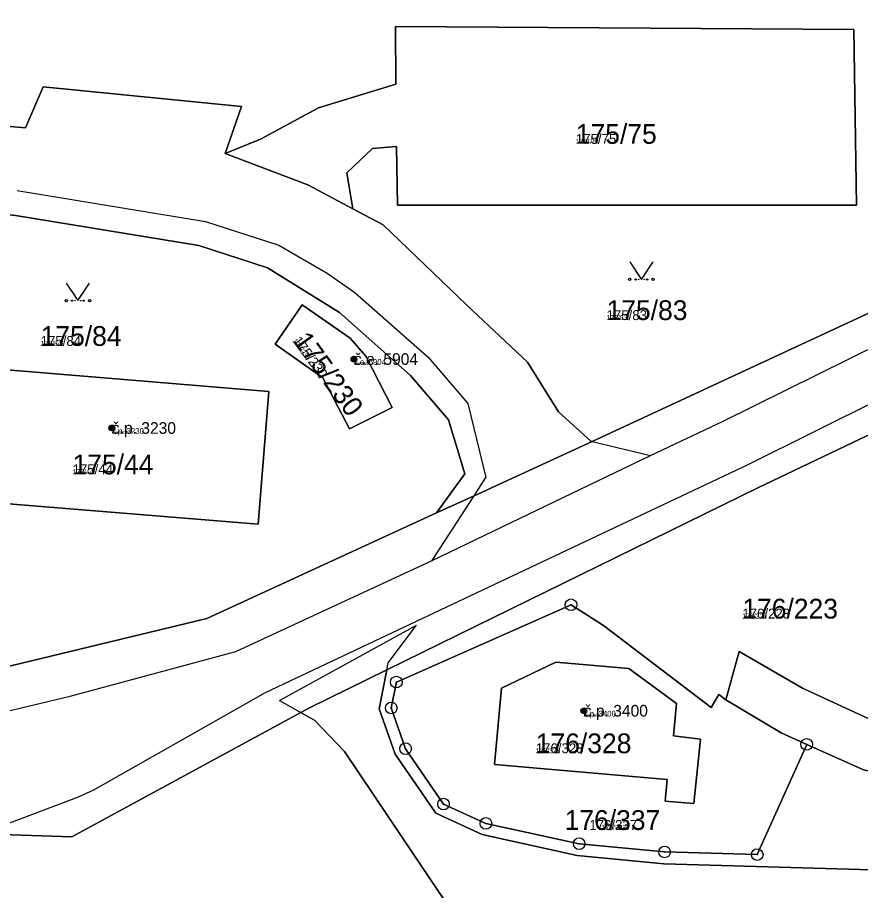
# Model space of a CAD drawing. Extents: x -759873 to -758487, y -975024 to -973516.
# Drawn here: x -759456.7 to -759384.3, y -974781.5 to -974706.5 of the extents above; entities that cross this region are included whole.
import ezdxf

# ---------------------------------------------------------------- set-up
doc = ezdxf.new("R2010")
doc.units = 0
for name, color, linetype in [('KAT_02_hranice parcel', 7, 'Continuous'), ('KAT_03_1000_st čísla parcelní', 7, 'Continuous'), ('KAT_03_1000_čísla parcelní', 7, 'Continuous'), ('KAT_03_1000_čísla popisná', 7, 'Continuous'), ('KAT_03_250_st čísla parcelní', 7, 'Continuous'), ('KAT_03_250_čísla parcelní', 7, 'Continuous'), ('KAT_03_250_čísla popisná', 7, 'Continuous'), ('KAT_03_500_st čísla parcelní', 7, 'Continuous'), ('KAT_03_500_čísla parcelní', 7, 'Continuous'), ('KAT_03_500_čísla popisná', 7, 'Continuous'), ('KAT_04_vnitřní kresba', 7, 'Continuous'), ('KAT_05_1000_značky kultur', 7, 'Continuous'), ('KAT_05_250_značky kultur', 7, 'Continuous'), ('KAT_05_500_značky kultur', 7, 'Continuous'), ('KAT_07_1000_značky budov', 7, 'Continuous'), ('KAT_07_250_značky budov', 7, 'Continuous'), ('KAT_07_500_značky budov', 7, 'Continuous'), ('KAT_11_značky bodu BP', 7, 'Continuous'), ('KAT_14_plocha_budovy', 7, 'Continuous'), ('KAT_14_plocha_pozemek', 7, 'Continuous')]:
    doc.layers.add(name, color=color, linetype=linetype)

msp = doc.modelspace()

# ---------------------------------------------------------------- linework, layer by layer
at = {"layer": 'KAT_02_hranice parcel'}
for points in [[(-759427.86, -974722.89), (-759428.36, -974719.79), (-759426.17, -974717.72), (-759424.11, -974717.53), (-759424.01, -974722.57), (-759384.61, -974722.59), (-759384.82, -974707.48), (-759424.18, -974707.23), (-759424.16, -974712.19), (-759430.82, -974714.21), (-759435.8, -974716.91), (-759438.82, -974718.15)], [(-759438.82, -974718.15), (-759437.43, -974714.11), (-759454.46, -974712.4), (-759455.96, -974715.95), (-759470.55, -974714.66), (-759468.01, -974711.71)], [(-759427.86, -974722.89), (-759431.72, -974720.83), (-759438.82, -974718.15)], [(-759338.69, -974720.79), (-759368.71, -974735.24), (-759393.08, -974746.85), (-759424.93, -974762.5)], [(-759407.29, -974742.88), (-759370.17, -974725.64), (-759360.14, -974721.06)], [(-759471.04, -974721.83), (-759456.84, -974723.48), (-759441.08, -974726.05), (-759435.18, -974727.96), (-759429.01, -974731.8), (-759422.91, -974737.21), (-759419.65, -974741.01), (-759418.24, -974745.66), (-759420.68, -974749.02)], [(-759407.29, -974742.88), (-759407.43, -974742.84), (-759410.19, -974740.33), (-759412.85, -974736.06), (-759418.1, -974731.15), (-759425.26, -974724.28), (-759427.86, -974722.89)], [(-759428.14, -974741.8), (-759430.42, -974737.4), (-759434.52, -974734.51), (-759432.2, -974731.13), (-759428.1, -974734), (-759426.75, -974735.54), (-759424.47, -974739.97), (-759428.14, -974741.8)], [(-759435.06, -974738.58), (-759458.61, -974736.64), (-759459.55, -974748.07), (-759436, -974749.98), (-759435.06, -974738.58)], [(-759420.68, -974749.02), (-759417.45, -974747.54), (-759407.29, -974742.88)], [(-759475.45, -974765.65), (-759470.53, -974765.37), (-759440.41, -974758.08), (-759420.68, -974749.02)], [(-759388.88, -974768.9), (-759393.13, -974778.37), (-759401.08, -974778.14), (-759408.42, -974777.43), (-759416.43, -974775.69), (-759420.07, -974774.03), (-759423.33, -974769.27), (-759424.56, -974765.77), (-759424.12, -974763.55), (-759409.12, -974756.91), (-759406.32, -974758.7), (-759397.07, -974765.74), (-759396.42, -974764.61), (-759395.83, -974765.08)], [(-759395.83, -974765.08), (-759394.67, -974760.92), (-759389.25, -974764.08), (-759382.92, -974767), (-759377.01, -974768.63)], [(-759400.31, -974768.17), (-759400.06, -974765.39), (-759404.15, -974762.39), (-759410.43, -974761.84), (-759415.09, -974764.06), (-759415.7, -974770.64), (-759400.86, -974771.92), (-759401.02, -974773.78), (-759398.56, -974773.98), (-759398.01, -974768.45), (-759400.31, -974768.17)], [(-759424.93, -974762.5), (-759431.64, -974765.8), (-759432.32, -974766.17)], [(-759424.93, -974762.5), (-759425.59, -974765.85), (-759424.23, -974769.73), (-759420.74, -974774.82), (-759416.74, -974776.65), (-759408.58, -974778.44), (-759401.14, -974779.15), (-759383.31, -974779.68), (-759360.24, -974780.18), (-759335.92, -974780.61), (-759318.75, -974781.06), (-759302.75, -974781.4)], [(-759395.83, -974765.08), (-759391.07, -974767.92), (-759388.88, -974768.9)], [(-759432.32, -974766.17), (-759452, -974776.85), (-759459.82, -974776.57), (-759471.04, -974776.07), (-759473.09, -974776.05)], [(-759413.3, -974803.92), (-759416.77, -974803.71), (-759416.1, -974790.31), (-759417.02, -974787.38), (-759418.5, -974784.52), (-759428.57, -974769.5), (-759431.12, -974766.84), (-759432.32, -974766.17)], [(-759355.39, -974773.73), (-759364.83, -974773.31), (-759375.96, -974772.8), (-759384.01, -974771.08), (-759388.88, -974768.9)]]:
    msp.add_lwpolyline(points, dxfattribs=at)
at = {"layer": 'KAT_03_1000_čísla popisná'}
for centre in [(-759427.76, -974735.8), (-759448.55, -974741.72), (-759408.02, -974766.01)]:
    msp.add_circle(centre, 0.25, dxfattribs=at)
at = {"layer": 'KAT_03_250_čísla popisná'}
for centre in [(-759427.76, -974735.8), (-759448.55, -974741.72), (-759408.02, -974766.01)]:
    msp.add_circle(centre, 0.0625, dxfattribs=at)
at = {"layer": 'KAT_03_500_čísla popisná'}
for centre in [(-759427.76, -974735.8), (-759448.55, -974741.72), (-759408.02, -974766.01)]:
    msp.add_circle(centre, 0.125, dxfattribs=at)
at = {"layer": 'KAT_04_vnitřní kresba'}
for p, q in [((-759456.68, -974721.32), (-759440.52, -974723.97)), ((-759440.52, -974723.97), (-759434.22, -974726.01)), ((-759434.22, -974726.01), (-759430.06, -974728.42)), ((-759430.06, -974728.42), (-759427.68, -974730.09)), ((-759396.05, -974741.14), (-759369.64, -974728.06)), ((-759427.68, -974730.09), (-759421.39, -974735.63)), ((-759393.91, -974744.86), (-759368.86, -974732.4)), ((-759421.39, -974735.63), (-759417.98, -974739.61)), ((-759417.98, -974739.61), (-759416.44, -974745.97)), ((-759402.28, -974744.08), (-759396.05, -974741.14)), ((-759407.29, -974742.88), (-759402.28, -974744.08)), ((-759421.03, -974753.09), (-759402.28, -974744.08)), ((-759435.37, -974764.44), (-759393.91, -974744.86)), ((-759417.45, -974747.54), (-759416.44, -974745.97)), ((-759421.03, -974753.09), (-759417.45, -974747.54)), ((-759437.91, -974760.91), (-759421.03, -974753.09)), ((-759434.15, -974765.14), (-759422.39, -974758.65)), ((-759424.81, -974761.9), (-759422.39, -974758.65)), ((-759452.12, -974764.75), (-759437.91, -974760.91)), ((-759424.93, -974762.5), (-759424.81, -974761.9)), ((-759450.09, -974772.8), (-759435.37, -974764.44)), ((-759470.25, -974769.11), (-759452.12, -974764.75)), ((-759434.15, -974765.14), (-759432.32, -974766.17)), ((-759459.82, -974776.57), (-759451.42, -974773.41)), ((-759451.42, -974773.41), (-759450.09, -974772.8))]:
    msp.add_line(p, q, dxfattribs=at)
at = {"layer": 'KAT_05_1000_značky kultur'}
for points in [[(-759404.07, -974727.459), (-759403.07, -974728.96), (-759402.07, -974727.459)], [(-759452.47, -974729.279), (-759451.47, -974730.78), (-759450.47, -974729.279)]]:
    msp.add_lwpolyline(points, dxfattribs=at)
for centre in [(-759404.07, -974728.959), (-759402.07, -974728.959), (-759452.47, -974730.779), (-759450.47, -974730.779)]:
    msp.add_circle(centre, 0.1, dxfattribs=at)
at = {"layer": 'KAT_05_250_značky kultur'}
for points in [[(-759403.32, -974728.585), (-759403.07, -974728.96), (-759402.82, -974728.585)], [(-759451.72, -974730.405), (-759451.47, -974730.78), (-759451.22, -974730.405)]]:
    msp.add_lwpolyline(points, dxfattribs=at)
for centre in [(-759403.32, -974728.96), (-759402.82, -974728.96), (-759451.72, -974730.78), (-759451.22, -974730.78)]:
    msp.add_circle(centre, 0.025, dxfattribs=at)
at = {"layer": 'KAT_05_500_značky kultur'}
for points in [[(-759403.57, -974728.209), (-759403.07, -974728.96), (-759402.57, -974728.209)], [(-759451.97, -974730.03), (-759451.47, -974730.78), (-759450.97, -974730.03)]]:
    msp.add_lwpolyline(points, dxfattribs=at)
for centre in [(-759403.57, -974728.96), (-759402.57, -974728.96), (-759451.97, -974730.78), (-759450.97, -974730.78)]:
    msp.add_circle(centre, 0.05, dxfattribs=at)
at = {"layer": 'KAT_07_1000_značky budov'}
for centre in [(-759427.767, -974735.799), (-759448.557, -974741.719), (-759408.027, -974766.009)]:
    msp.add_circle(centre, 0.175, dxfattribs=at)
at = {"layer": 'KAT_07_250_značky budov'}
for centre in [(-759427.762, -974735.8), (-759448.552, -974741.72), (-759408.022, -974766.01)]:
    msp.add_circle(centre, 0.0437, dxfattribs=at)
at = {"layer": 'KAT_07_500_značky budov'}
for centre in [(-759427.763, -974735.8), (-759448.553, -974741.72), (-759408.023, -974766.01)]:
    msp.add_circle(centre, 0.0875, dxfattribs=at)
at = {"layer": 'KAT_11_značky bodu BP'}
for centre, radius in [((-759409.12, -974756.91), 0.5), ((-759409.12, -974756.91), 0.0303), ((-759424.12, -974763.55), 0.5), ((-759424.12, -974763.55), 0.0303), ((-759424.56, -974765.77), 0.5), ((-759424.56, -974765.77), 0.0303), ((-759423.33, -974769.27), 0.5), ((-759388.88, -974768.9), 0.5), ((-759388.88, -974768.9), 0.0303), ((-759423.33, -974769.27), 0.0303), ((-759420.07, -974774.03), 0.5), ((-759420.07, -974774.03), 0.0303), ((-759416.43, -974775.69), 0.5), ((-759416.43, -974775.69), 0.0303), ((-759408.42, -974777.43), 0.5), ((-759408.42, -974777.43), 0.0303), ((-759401.08, -974778.14), 0.5), ((-759393.13, -974778.37), 0.5), ((-759401.08, -974778.14), 0.0303), ((-759393.13, -974778.37), 0.0303)]:
    msp.add_circle(centre, radius, dxfattribs=at)
at = {"layer": 'KAT_14_plocha_budovy'}
for points in [[(-759434.52, -974734.51), (-759430.42, -974737.4), (-759428.14, -974741.8), (-759424.47, -974739.97), (-759426.75, -974735.54), (-759428.1, -974734), (-759432.2, -974731.13)], [(-759436, -974749.98), (-759435.06, -974738.58), (-759458.61, -974736.64), (-759459.55, -974748.07)], [(-759410.43, -974761.84), (-759415.09, -974764.06), (-759415.7, -974770.64), (-759400.86, -974771.92), (-759401.02, -974773.78), (-759398.56, -974773.98), (-759398.01, -974768.45), (-759400.31, -974768.17), (-759400.06, -974765.39), (-759404.15, -974762.39)]]:
    msp.add_lwpolyline(points, close=True, dxfattribs=at)
at = {"layer": 'KAT_14_plocha_pozemek'}
for points in [[(-759272.2, -974639.41), (-759281.65, -974658.4), (-759285.91, -974664.61), (-759289.93, -974671.68), (-759292.94, -974676.6), (-759294.74, -974679.54), (-759302.19, -974688.3), (-759308.07, -974693.53), (-759315.75, -974698.43), (-759315.34, -974698.65), (-759317.07, -974700.43), (-759318.71, -974700.17), (-759321.9, -974701.95), (-759356.72, -974718.32), (-759357.54, -974720.88), (-759360.14, -974721.06), (-759370.17, -974725.64), (-759407.29, -974742.88), (-759417.45, -974747.54), (-759420.68, -974749.02), (-759440.41, -974758.08), (-759470.53, -974765.37)], [(-759459.82, -974776.57), (-759452, -974776.85), (-759432.32, -974766.17), (-759431.64, -974765.8), (-759424.93, -974762.5), (-759393.08, -974746.85), (-759368.71, -974735.24), (-759338.69, -974720.79), (-759334.79, -974718.9), (-759324.54, -974713.59), (-759321.22, -974711.76), (-759310.73, -974705.56), (-759302.37, -974699.71), (-759294.92, -974692.6), (-759285.8, -974680.51), (-759284.4, -974678.27), (-759283.65, -974677.06), (-759283.26, -974675.23), (-759282.29, -974673.85), (-759279.86, -974670.39), (-759274.06, -974660.4), (-759274.03, -974662.11), (-759273.99, -974664.17)], [(-759470.55, -974714.66), (-759455.96, -974715.95), (-759454.46, -974712.4), (-759437.43, -974714.11), (-759438.82, -974718.15), (-759435.8, -974716.91), (-759430.82, -974714.21), (-759424.16, -974712.19), (-759424.18, -974707.23), (-759384.82, -974707.48), (-759384.61, -974722.59), (-759424.01, -974722.57), (-759424.11, -974717.53), (-759426.17, -974717.72), (-759428.36, -974719.79), (-759427.86, -974722.89), (-759425.26, -974724.28), (-759418.1, -974731.15), (-759412.85, -974736.06), (-759410.19, -974740.33), (-759407.43, -974742.84), (-759407.29, -974742.88), (-759370.17, -974725.64)], [(-759456.84, -974723.48), (-759441.08, -974726.05), (-759435.18, -974727.96), (-759429.01, -974731.8), (-759422.91, -974737.21), (-759419.65, -974741.01), (-759418.24, -974745.66), (-759420.68, -974749.02), (-759417.45, -974747.54), (-759407.29, -974742.88), (-759407.43, -974742.84), (-759410.19, -974740.33), (-759412.85, -974736.06), (-759418.1, -974731.15), (-759425.26, -974724.28), (-759427.86, -974722.89), (-759431.72, -974720.83), (-759438.82, -974718.15), (-759437.43, -974714.11), (-759454.46, -974712.4), (-759455.96, -974715.95), (-759470.55, -974714.66)], [(-759368.71, -974735.24), (-759393.08, -974746.85), (-759424.93, -974762.5), (-759425.59, -974765.85), (-759424.23, -974769.73), (-759420.74, -974774.82), (-759416.74, -974776.65), (-759408.58, -974778.44), (-759401.14, -974779.15), (-759383.31, -974779.68)], [(-759384.01, -974771.08), (-759388.88, -974768.9), (-759393.13, -974778.37), (-759401.08, -974778.14), (-759408.42, -974777.43), (-759416.43, -974775.69), (-759420.07, -974774.03), (-759423.33, -974769.27), (-759424.56, -974765.77), (-759424.12, -974763.55), (-759409.12, -974756.91), (-759406.32, -974758.7), (-759397.07, -974765.74), (-759396.42, -974764.61), (-759395.83, -974765.08), (-759394.67, -974760.92), (-759389.25, -974764.08), (-759382.92, -974767)], [(-759293.44, -974780.74), (-759301.03, -974781.35), (-759301.24, -974780.99), (-759302.75, -974781.4), (-759318.75, -974781.06), (-759335.92, -974780.61), (-759360.24, -974780.18), (-759383.31, -974779.68), (-759401.14, -974779.15), (-759408.58, -974778.44), (-759416.74, -974776.65), (-759420.74, -974774.82), (-759424.23, -974769.73), (-759425.59, -974765.85), (-759424.93, -974762.5), (-759431.64, -974765.8), (-759432.32, -974766.17), (-759431.12, -974766.84), (-759428.57, -974769.5), (-759418.5, -974784.52)], [(-759457.57, -974808.53), (-759456.64, -974812.53), (-759452.15, -974812.73), (-759451.85, -974804.87), (-759439.43, -974805.38), (-759439.72, -974812.56), (-759437.92, -974812.63), (-759437.93, -974812.98), (-759434.58, -974813.37), (-759419.38, -974814), (-759414.25, -974806.06), (-759413.3, -974803.92), (-759416.77, -974803.71), (-759416.1, -974790.31), (-759417.02, -974787.38), (-759418.5, -974784.52), (-759428.57, -974769.5), (-759431.12, -974766.84), (-759432.32, -974766.17), (-759452, -974776.85), (-759459.82, -974776.57)]]:
    msp.add_lwpolyline(points, dxfattribs=at)
for points in [[(-759424.16, -974712.19), (-759430.82, -974714.21), (-759435.8, -974716.91), (-759438.82, -974718.15), (-759431.72, -974720.83), (-759427.86, -974722.89), (-759428.36, -974719.79), (-759426.17, -974717.72), (-759424.11, -974717.53), (-759424.01, -974722.57), (-759384.61, -974722.59), (-759384.82, -974707.48), (-759424.18, -974707.23)], [(-759420.68, -974749.02), (-759418.24, -974745.66), (-759419.65, -974741.01), (-759422.91, -974737.21), (-759429.01, -974731.8), (-759435.18, -974727.96), (-759441.08, -974726.05), (-759456.84, -974723.48), (-759471.04, -974721.83), (-759474.56, -974756.83), (-759475.45, -974765.65), (-759470.53, -974765.37), (-759440.41, -974758.08)], [(-759428.14, -974741.8), (-759430.42, -974737.4), (-759434.52, -974734.51), (-759432.2, -974731.13), (-759428.1, -974734), (-759426.75, -974735.54), (-759424.47, -974739.97)], [(-759428.14, -974741.8), (-759424.47, -974739.97), (-759426.75, -974735.54), (-759428.1, -974734), (-759432.2, -974731.13), (-759434.52, -974734.51), (-759430.42, -974737.4)], [(-759435.06, -974738.58), (-759436, -974749.98), (-759459.55, -974748.07), (-759458.61, -974736.64)], [(-759435.06, -974738.58), (-759458.61, -974736.64), (-759459.55, -974748.07), (-759436, -974749.98)], [(-759388.88, -974768.9), (-759391.07, -974767.92), (-759395.83, -974765.08), (-759396.42, -974764.61), (-759397.07, -974765.74), (-759406.32, -974758.7), (-759409.12, -974756.91), (-759424.12, -974763.55), (-759424.56, -974765.77), (-759423.33, -974769.27), (-759420.07, -974774.03), (-759416.43, -974775.69), (-759408.42, -974777.43), (-759401.08, -974778.14), (-759393.13, -974778.37)], [(-759388.88, -974768.9), (-759384.01, -974771.08), (-759375.96, -974772.8), (-759364.83, -974773.31), (-759355.39, -974773.73), (-759355.03, -974764.72), (-759360.28, -974764.39), (-759361.45, -974764.42), (-759361.64, -974764.95), (-759366.99, -974764.83), (-759368.7, -974765.06), (-759373.86, -974768.88), (-759377.01, -974768.63), (-759382.92, -974767), (-759389.25, -974764.08), (-759394.67, -974760.92), (-759395.83, -974765.08), (-759391.07, -974767.92)], [(-759400.31, -974768.17), (-759400.06, -974765.39), (-759404.15, -974762.39), (-759410.43, -974761.84), (-759415.09, -974764.06), (-759415.7, -974770.64), (-759400.86, -974771.92), (-759401.02, -974773.78), (-759398.56, -974773.98), (-759398.01, -974768.45)], [(-759400.31, -974768.17), (-759398.01, -974768.45), (-759398.56, -974773.98), (-759401.02, -974773.78), (-759400.86, -974771.92), (-759415.7, -974770.64), (-759415.09, -974764.06), (-759410.43, -974761.84), (-759404.15, -974762.39), (-759400.06, -974765.39)]]:
    msp.add_lwpolyline(points, close=True, dxfattribs=at)

# ---------------------------------------------------------------- texts
at = {"layer": 'KAT_03_1000_st čísla parcelní'}
msp.add_text('175/230', height=1.7, rotation=306, dxfattribs=at).set_placement((-759433.057, -974734.239))
for s, p in [('175/44', (-759451.93, -974745.7)), ('176/328', (-759412.15, -974769.66))]:
    msp.add_text(s, height=1.7, dxfattribs=at).set_placement(p)
at = {"layer": 'KAT_03_1000_čísla parcelní'}
for s, p in [('175/75', (-759408.71, -974717.309)), ('175/83', (-759406.07, -974732.45)), ('175/84', (-759454.67, -974734.669)), ('176/223', (-759394.41, -974758.09)), ('176/337', (-759409.668, -974776.25))]:
    msp.add_text(s, height=1.7, dxfattribs=at).set_placement(p)
at = {"layer": 'KAT_03_1000_čísla popisná'}
for s, p in [('č.e. 5904', (-759427.76, -974736.3)), ('č.p. 3230', (-759448.55, -974742.22)), ('č.p. 3400', (-759408.02, -974766.51))]:
    msp.add_text(s, height=1, dxfattribs=at).set_placement(p)
at = {"layer": 'KAT_03_250_st čísla parcelní'}
msp.add_text('175/230', height=0.425, rotation=306, dxfattribs=at).set_placement((-759433.057, -974734.239))
for s, p in [('175/44', (-759451.93, -974745.7)), ('176/328', (-759412.15, -974769.66))]:
    msp.add_text(s, height=0.425, dxfattribs=at).set_placement(p)
at = {"layer": 'KAT_03_250_čísla parcelní'}
for s, p in [('175/75', (-759408.71, -974717.309)), ('175/83', (-759406.07, -974732.45)), ('175/84', (-759454.67, -974734.669)), ('176/223', (-759394.41, -974758.09)), ('176/337', (-759406.49, -974776.25))]:
    msp.add_text(s, height=0.425, dxfattribs=at).set_placement(p)
at = {"layer": 'KAT_03_250_čísla popisná'}
for s, p in [('č.e. 5904', (-759427.76, -974736.3)), ('č.p. 3230', (-759448.55, -974742.22)), ('č.p. 3400', (-759408.02, -974766.51))]:
    msp.add_text(s, height=0.25, dxfattribs=at).set_placement(p)
at = {"layer": 'KAT_03_500_st čísla parcelní'}
msp.add_text('175/230', height=0.85, rotation=306, dxfattribs=at).set_placement((-759433.057, -974734.239))
for s, p in [('175/44', (-759451.93, -974745.7)), ('176/328', (-759412.15, -974769.66))]:
    msp.add_text(s, height=0.85, dxfattribs=at).set_placement(p)
at = {"layer": 'KAT_03_500_čísla parcelní'}
for s, p in [('175/75', (-759408.71, -974717.309)), ('175/83', (-759406.07, -974732.45)), ('175/84', (-759454.67, -974734.669)), ('176/223', (-759394.41, -974758.09)), ('176/337', (-759407.549, -974776.25))]:
    msp.add_text(s, height=0.85, dxfattribs=at).set_placement(p)
at = {"layer": 'KAT_03_500_čísla popisná'}
for s, p in [('č.e. 5904', (-759427.76, -974736.3)), ('č.p. 3230', (-759448.55, -974742.22)), ('č.p. 3400', (-759408.02, -974766.51))]:
    msp.add_text(s, height=0.5, dxfattribs=at).set_placement(p)

doc.saveas('drawing.dxf')
